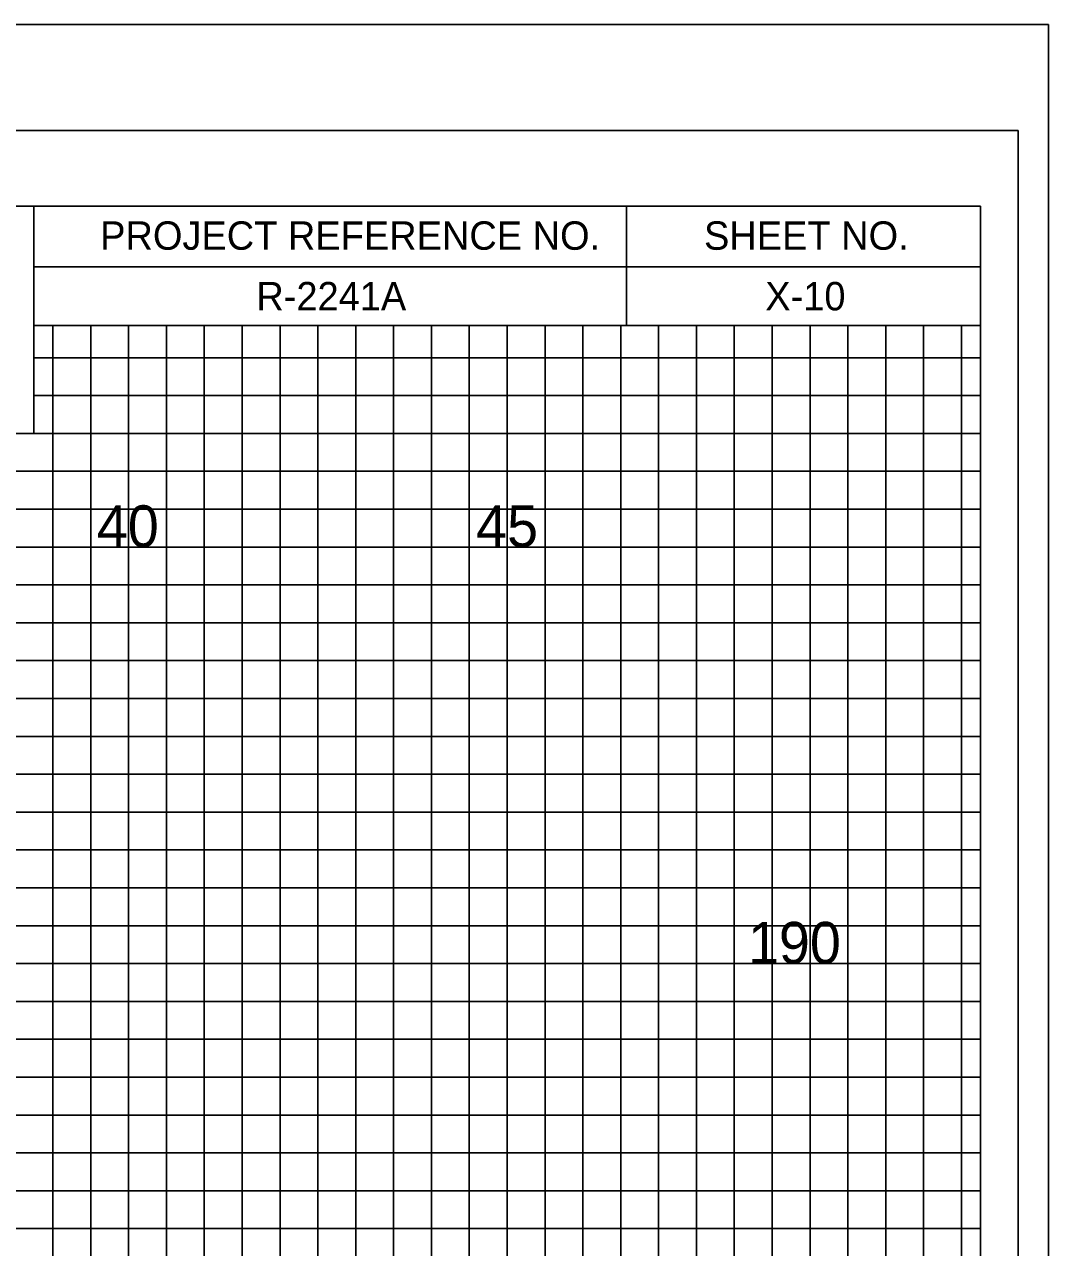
# Model space of a CAD drawing. Extents: x -4 to 103, y -2 to 6583.
# Drawn here: x 89.88 to 103.4, y 688.68 to 704.83 of the extents above; entities that cross this region are included whole.
import ezdxf

# ---------------------------------------------------------------- set-up
doc = ezdxf.new("R2010")
doc.units = 0
for name, color, linetype in [('Prop XS Elevation Labels', 7, 'Continuous'), ('Prop XS Offset Labels', 7, 'Continuous'), ('Prop XS Project Number', 7, 'Continuous'), ('Prop XS Sheet Number', 7, 'Continuous'), ('Sheet Cross Section CELL', 7, 'Continuous'), ('Sheet Cross Section Grid Major CELL', 7, 'Continuous'), ('Sheet Cross Section Grid Middle CELL', 7, 'Continuous'), ('Sheet Cutting Line CELL', 7, 'Continuous'), ('Sheet DOT Grid CELL', 7, 'Continuous'), ('Sheet Plot Border Inside CELL', 7, 'Continuous'), ('Sheet Plot Border Outside CELL', 7, 'Continuous')]:
    doc.layers.add(name, color=color, linetype=linetype)

msp = doc.modelspace()

# ---------------------------------------------------------------- linework, layer by layer
at = {"layer": 'Sheet Cross Section CELL'}
for p, q in [((90, 702.425), (102.5, 702.425)), ((90, 702.425), (102.5, 702.425)), ((97.825, 700.85), (97.825, 702.425)), ((101.875, 702.425), (101.875, 702.425)), ((102.5, 702.425), (102.5, 702.425)), ((102.5, 700.85), (102.5, 702.425)), ((102.5, 702.425), (102.5, 702.425)), ((102.5, 702.425), (102.5, 702.425)), ((102.5, 700.85), (102.5, 702.425)), ((90, 701.625), (102.5, 701.625)), ((90, 700.85), (102.5, 700.85)), ((99.4, 700.85), (99.4, 700.85)), ((99.4, 700.85), (99.4, 700.85))]:
    msp.add_line(p, q, dxfattribs=at)
for points in [[(102.5, 702.425), (0, 702.425), (0, 637.425), (102.5, 637.425)], [(83.75, 702.425), (90, 702.425), (90, 699.425), (83.75, 699.425)]]:
    msp.add_lwpolyline(points, close=True, dxfattribs=at)
at = {"layer": 'Sheet Cross Section Grid Major CELL'}
for points in [[(91.25, 637.425), (91.25, 700.85), (93.75, 700.85), (93.75, 637.425)], [(96.25, 637.425), (96.25, 700.85), (98.75, 700.85), (98.75, 637.425)], [(101.25, 637.425), (101.25, 700.85)], [(90, 699.925), (102.5, 699.925)], [(0, 694.925), (102.5, 694.925), (102.5, 697.425), (0, 697.425)], [(0, 689.925), (102.5, 689.925), (102.5, 692.425), (0, 692.425)]]:
    msp.add_lwpolyline(points, dxfattribs=at)
at = {"layer": 'Sheet Cross Section Grid Middle CELL'}
for points in [[(90.25, 637.425), (90.25, 700.85), (90.75, 700.85), (90.75, 637.425)], [(91.75, 637.425), (91.75, 700.85), (92.25, 700.85), (92.25, 637.425)], [(92.75, 637.425), (92.75, 700.85), (93.25, 700.85), (93.25, 637.425)], [(94.25, 637.425), (94.25, 700.85), (94.75, 700.85), (94.75, 637.425)], [(95.25, 637.425), (95.25, 700.85), (95.75, 700.85), (95.75, 637.425)], [(96.75, 637.425), (96.75, 700.85), (97.25, 700.85), (97.25, 637.425)], [(97.75, 637.425), (97.75, 700.85), (98.25, 700.85), (98.25, 637.425)], [(99.25, 637.425), (99.25, 700.85), (99.75, 700.85), (99.75, 637.425)], [(100.25, 637.425), (100.25, 700.85)], [(100.25, 700.85), (100.75, 700.85), (100.75, 637.425), (101.75, 637.425), (101.75, 700.85), (102.25, 700.85), (102.25, 637.425)], [(102.5, 699.425), (102.5, 700.425), (90, 700.425)], [(0, 698.925), (102.5, 698.925), (102.5, 699.425), (0, 699.425)], [(0, 697.925), (102.5, 697.925), (102.5, 698.425), (0, 698.425)], [(0, 696.425), (102.5, 696.425), (102.5, 696.925), (0, 696.925)], [(0, 695.425), (102.5, 695.425), (102.5, 695.925), (0, 695.925)], [(0, 693.925), (102.5, 693.925), (102.5, 694.425), (0, 694.425)], [(0, 692.925), (102.5, 692.925), (102.5, 693.425), (0, 693.425)], [(0, 691.425), (102.5, 691.425), (102.5, 691.925), (0, 691.925)], [(0, 690.425), (102.5, 690.425), (102.5, 690.925), (0, 690.925)], [(0, 688.925), (102.5, 688.925), (102.5, 689.425), (0, 689.425)]]:
    msp.add_lwpolyline(points, dxfattribs=at)
at = {"layer": 'Sheet Cutting Line CELL'}
msp.add_line((-3.5, 704.825), (103.4, 704.825), dxfattribs=at)
at = {"layer": 'Sheet DOT Grid CELL'}
for p, q in [((91.25, 637.425), (91.25, 700.85)), ((93.75, 637.425), (93.75, 700.85)), ((96.25, 637.425), (96.25, 700.85)), ((98.75, 637.425), (98.75, 700.85)), ((101.25, 637.425), (101.25, 700.85)), ((90, 699.925), (102.5, 699.925)), ((0, 697.425), (102.5, 697.425)), ((0, 694.925), (102.5, 694.925)), ((0, 692.425), (102.5, 692.425)), ((0, 689.925), (102.5, 689.925))]:
    msp.add_line(p, q, dxfattribs=at)
at = {"layer": 'Sheet Plot Border Inside CELL'}
msp.add_lwpolyline([(103, 703.425), (-2.8, 703.425), (-2.8, 636.425), (103, 636.425)], close=True, dxfattribs=at)
at = {"layer": 'Sheet Plot Border Outside CELL'}
msp.add_lwpolyline([(103.4, 704.825), (-3.5, 704.825), (-3.5, 635), (103.4, 635)], close=True, dxfattribs=at)

# ---------------------------------------------------------------- texts
at = {"layer": 'Prop XS Elevation Labels'}
msp.add_text('190', height=0.55, dxfattribs=at).set_placement((99.43, 692.425))
at = {"layer": 'Prop XS Offset Labels'}
for s, p in [('40', (90.831, 697.925)), ('45', (95.84, 697.925))]:
    msp.add_text(s, height=0.55, dxfattribs=at).set_placement(p)
at = {"layer": 'Prop XS Project Number'}
msp.add_text('R-2241A', height=0.375, dxfattribs=at).set_placement((92.938, 701.05))
at = {"layer": 'Prop XS Sheet Number'}
msp.add_text('X-10', height=0.375, dxfattribs=at).set_placement((99.659, 701.05))
at = {"layer": 'Sheet Cross Section CELL'}
for s, p in [('PROJECT REFERENCE NO.', (90.875, 701.85)), ('SHEET NO.', (98.85, 701.85))]:
    msp.add_text(s, height=0.375, dxfattribs=at).set_placement(p)

doc.saveas('drawing.dxf')
